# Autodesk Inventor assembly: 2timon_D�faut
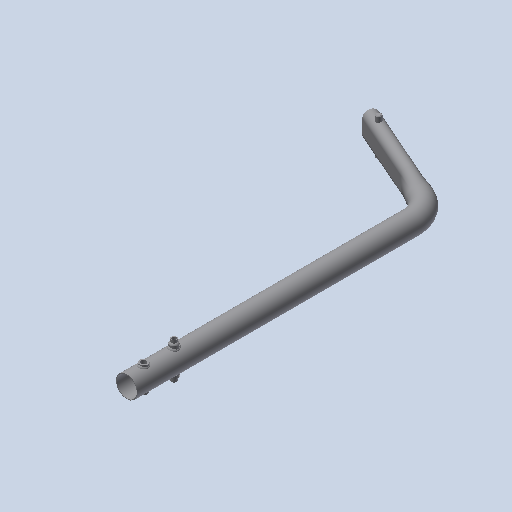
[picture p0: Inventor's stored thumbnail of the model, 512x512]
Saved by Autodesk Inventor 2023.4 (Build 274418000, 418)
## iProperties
Created: 2011-01
Part Number: 2timon_D�faut
Document SubType Name: Assembly
Designer: eric
Mass: 68.6923 g
Surface Area: 1295.09 cm^2
Volume: 68.6923 cm^3
Density: 1 g/cm^3
Author: eric
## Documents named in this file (12)
- C:\Users\bruno\Documents\1-Cours-2024-25\TSsI\7-Dynamique\chariot de golf\chariot_de_golf\chariot_de_golf_trolem\2timon_Defaut.iam
- C:\Users\bruno\Documents\1-Cours-2024-25\TSsI\7-Dynamique\chariot de golf\chariot_de_golf\chariot_de_golf_trolem\bossage3_Defaut.ipt
- C:\Users\bruno\Documents\1-Cours-2024-25\TSsI\7-Dynamique\chariot de golf\chariot_de_golf\chariot_de_golf_trolem\bossage1_Defaut.ipt
- C:\Users\bruno\Documents\1-Cours-2024-25\TSsI\7-Dynamique\chariot de golf\chariot_de_golf\chariot_de_golf_trolem\bead31_Defaut.ipt
- C:\Users\bruno\Documents\1-Cours-2024-25\TSsI\7-Dynamique\chariot de golf\chariot_de_golf\chariot_de_golf_trolem\bossage2_Defaut.ipt
- C:\Users\bruno\Documents\1-Cours-2024-25\TSsI\7-Dynamique\chariot de golf\chariot_de_golf\chariot_de_golf_trolem\bead36_Defaut.ipt
- C:\Users\bruno\Documents\1-Cours-2024-25\TSsI\7-Dynamique\chariot de golf\chariot_de_golf\chariot_de_golf_trolem\2timon_tube_Defaut.ipt
- C:\Users\bruno\Documents\1-Cours-2024-25\TSsI\7-Dynamique\chariot de golf\chariot_de_golf\chariot_de_golf_trolem\bead35_Defaut.ipt
- C:\Users\bruno\Documents\1-Cours-2024-25\TSsI\7-Dynamique\chariot de golf\chariot_de_golf\chariot_de_golf_trolem\bead33_Defaut.ipt
- C:\Users\bruno\Documents\1-Cours-2024-25\TSsI\7-Dynamique\chariot de golf\chariot_de_golf\chariot_de_golf_trolem\bead34_Defaut.ipt
- C:\Users\bruno\Documents\1-Cours-2024-25\TSsI\7-Dynamique\chariot de golf\chariot_de_golf\chariot_de_golf_trolem\48Axe_8_55_Defaut.ipt
- C:\Users\bruno\Documents\1-Cours-2024-25\TSsI\7-Dynamique\chariot de golf\chariot_de_golf\chariot_de_golf_trolem\bead30_Defaut.ipt
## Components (11 placed, 11 different names)
1. bossage3_Defaut:1
2. bossage1_Defaut:1
3. bead31_Defaut:1
4. bossage2_Defaut:1
5. bead36_Defaut:1
6. 2timon_tube_Defaut:1
7. bead35_Defaut:1
8. bead33_Defaut:1
9. bead34_Defaut:1
10. 48Axe_8_55_Defaut:1
11. bead30_Defaut:1
